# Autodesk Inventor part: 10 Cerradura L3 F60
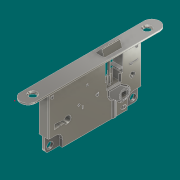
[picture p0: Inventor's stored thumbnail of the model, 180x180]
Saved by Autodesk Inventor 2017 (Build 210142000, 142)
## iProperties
Created: 2019-09
Part Number: 10 Cerradura L3 F60
Material: Acero inoxidable
Document SubType Name: Modeling
Designer: Alfredo Castillo
Density: 8 g/cm^3
Appearance: Semipulido
Mass: 1146.85 g
Surface Area: 306.712 cm^2
Volume: 143.356 cm^3
Author: Alfredo Castillo
Comments: Proveedor ITALINNEA Producto CERRADURA L3 F60 Y F30 CONTRAFUEGO Marca AGB (ITALIA) Modelo -Sin información- Material ACERO ZINCADO Terminación NIQUELADA Instalación Perforar madera por el canto de la 
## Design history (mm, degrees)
sketch "Boceto1"
  geometry: L1 (0, 0)-(0, 195); L2 (11, 11)-(11, 184); L3 (-11, 184)-(-11, 11); C1 r 4.5 at (0, 177.5); C2 r 4.5 at (0, 17.5); A1 r 11 centre (0, 11) between (-11, 11) and (11, 11); A2 r 11 centre (0, 184) between (11, 184) and (-11, 184); 1 further point
  constraints: 8 end point, 6 point on circle, 4 centre point, 4 point on line, 4 tangent, 1 midpoint, 1 parallel, 1 vertical
  dimensions: "d0" = 195 distance of L1.start L1.end; "d1" = 22 diameter of A2; "d2" = 9 diameter of C1; "d3" = 9 diameter of C2; "d4" = 160 distance of C2.centre C1.centre; "d5" = 17.5 distance of L1.end C1.centre (= -0.5 x d4 + 0.5 x d0)
extrude "Extrusión1" new body sketch "Boceto1" distance "d6" = 3; taper "d7" = 0 deg
chamfer "Chaflán1" distance "d8" = 1.5; stored, may be unused: second distance "d9" = 2, angle "d10" = 45 deg
fillet "Empalme1" dims "d11" = 1
sketch "Boceto2"
  geometry: L1 (-7, 162.5)-(7, 162.5); L2 (7, 162.5)-(7, 32.5); L3 (7, 32.5)-(-7, 32.5); L4 (-7, 32.5)-(-7, 162.5); L5 (11, 11)-(11, 184) reference; 1 further point
  constraints: 8 end point, 2 parallel, 1 horizontal, 1 perpendicular
  dimensions: "d12" = 130 distance of L1.end L2.end; "d13" = 32.5 distance from line of point (0, 0) L3; "d16" = 14 distance of L1.start L1.end; "d17" = 4 distance between parallel lines of L5 L2
extrude "Extrusión2" join sketch "Boceto2" distance "d14" = 76; taper "d15" = 0 deg
sketch "Boceto5"
  geometry: L1 (0, 130)-(76, 130) reference; L2 (76, 130)-(76, 0) reference; L3 (56, 130)-(76, 130); L4 (76, 130)-(76, 110); L5 (76, 20)-(76, 0); L6 (76, 0)-(56, 0); L7 (0, 0)-(76, 0) reference; A1 r 20 centre (76, 130) between (56, 130) and (76, 110); A2 r 20 centre (76, 0) between (76, 20) and (56, 0); 1 further point
  constraints: 8 end point, 4 point on circle, 3 collinear, 2 centre point, 2 point on line, 1 horizontal
  dimensions: "d21" = 20 radius of A1; "d22" = 20 radius of A2
sketch "Boceto3"
  geometry: L1 (0, 130)-(-76, 130) reference; L2 (-76, 0)-(-76, 130) reference; L3 (-76, 110)-(-76, 130); L4 (-76, 130)-(-56, 130); L5 (-76, 20)-(-76, 0); L6 (-76, 0)-(-56, 0); L7 (-56, 130)-(-56, 120); L8 (-76, 110)-(-66, 110); L9 (-76, 20)-(-66, 20); L10 (-56, 0)-(-56, 10); A1 r 10 centre (-66, 120) between (-66, 110) and (-56, 120); A2 r 10 centre (-66, 10) between (-56, 10) and (-66, 20); 1 further point
  constraints: 16 end point, 4 point on circle, 4 tangent, 2 centre point, 2 collinear, 2 horizontal, 2 perpendicular, 2 vertical, 1 point on line
  dimensions: "d233" = 10 distance of L4.end L7.end; "d234" = 10 distance of L3.start L8.end; "d235" = 10 distance of L5.start L9.end; "d236" = 10 distance of L6.end L10.end
extrude "Extrusión3" cut sketch "Boceto3" distance "d23" = 5; taper "d24" = 0 deg
fillet "Empalme2" dims "d27" = 5
hole "Agujero1" diameter "d31" = 9; stored, may be unused: countersink angle "d35" = 90 deg, drill point angle "d37" = 118 deg; dims "d29" = 7, "d30" = 7, "d32" = 6, "d33" = 4, "d34" = 2, "d36" = 8
hole "Agujero2" diameter "d40" = 9; stored, may be unused: countersink angle "d44" = 90 deg, drill point angle "d46" = 118 deg; dims "d38" = 7, "d39" = 7, "d41" = 6, "d42" = 4, "d43" = 2, "d45" = 8
fillet "Empalme4" dims "d47" = 1
fillet "Empalme5" dims "d48" = 1
fillet "Empalme7" dims "d50" = 1
sketch "Boceto6"
  geometry: L1 (-60.872, 105.498)-(-45.872, 105.498); L2 (-45.184, 109.399)-(-38, 99); L3 (0, 150.5)-(0, -22.5) reference; L4 (0, 129)-(-56, 129) reference; L5 (-61.027, 98.919)-(-51.427, 85.022); L6 (-45.668, 82)-(-38, 82); L7 (-38, 82)-(-38, 99); L8 (-57.646, 94.024)-(-76, 94.024); L9 (-76, 109)-(-76, 19) reference; L10 (-52.81, 87.024)-(-76, 87.024); L11 (-76, 94.024)-(-76, 87.024); A1 r 9.5 centre (-53, 104) between (-45.184, 109.399) and (-61.027, 98.919); A2 r 7 centre (-45.668, 89) between (-51.427, 85.022) and (-45.668, 82); 4 further points
  constraints: 16 end point, 4 point on circle, 3 horizontal, 3 point on line, 3 tangent, 2 centre point, 2 parallel, 1 collinear, 1 vertical
  dimensions: "d51" = 19 diameter of A1; "d54" = 53 distance from line of L3 A1.centre; "d55" = 25 distance from line of L4 A1.centre; "d59" = 7 radius of A2 (derived); "d60" = 7 distance between parallel lines of L8 L10; "d109" = 17 distance of L6.end L2.end; "d110" = 30 distance from line of L2.end L4; "d116" = 38 distance between parallel lines of L9 L7
extrude "Extrusión5" join sketch "Boceto6" distance "d61" = 1; taper "d62" = 0 deg
sketch "Boceto9"
  geometry: L1 (0, 7)-(1, 7) reference; L2 (0, 7)-(0, 0) reference; L3 (0, 0)-(1, 0) reference; L4 (1, 7)-(1, 0) reference; L5 (0, 7)-(1, 7) reference; 1 further point
extrude "Extrusión7" cut sketch "Boceto9" distance "d70" = 1; taper "d71" = 0 deg
fillet "Empalme13" dims "d72" = 3
fillet "Empalme14" dims "d73" = 1
sketch "Boceto10"
  geometry: L1 (-56.5, 107.5)-(-49.5, 107.5); L2 (-49.5, 107.5)-(-49.5, 100.5); L3 (-49.5, 100.5)-(-56.5, 100.5); L4 (-56.5, 100.5)-(-56.5, 107.5); L5 (-56.5, 107.5)-(-49.5, 100.5); L6 (-49.5, 107.5)-(-56.5, 100.5); 5 further points
  constraints: 12 end point, 2 midpoint, 2 parallel, 1 horizontal, 1 perpendicular, 1 other
  dimensions: "d74" = 7 distance of L2.end L3.end; "d75" = 7 distance of L1.end L2.end
extrude "Extrusión8" cut sketch "Boceto10" distance "d77" = 50; taper "d78" = 0 deg
sketch "Boceto11"
  geometry: C1 r 7 at (-53, 104); C2 r 6.75 at (-53, 104); 5 further points
  constraints: 2 centre point, 2 coincident, 1 other
  dimensions: "d79" = 14 diameter of C1; "d80" = 13.5 diameter of C2
extrude "Extrusión9" cut sketch "Boceto11" distance "d81" = 2; taper "d82" = 0 deg
fillet "Empalme15" dims "d83" = 1
sketch "Boceto12"
  geometry: L1 (-76, 4)-(-76, 124) reference; C1 r 3 at (-36, 116.356); 2 further points
  constraints: 1 centre point
  dimensions: "d84" = 6 diameter of C1; "d98" = 40 distance from line of L1 C1.centre
extrude "Extrusión10" join sketch "Boceto12" distance "d85" = 0.5; taper "d86" = 0 deg
fillet "Empalme16" dims "d87" = 1
sketch "Boceto13"
  geometry: C1 r 3 at (-36, 116.356) reference; C2 r 3.125 at (-36, 116.356); 1 further point
  constraints: 1 centre point, 1 coincident
  dimensions: "d88" = 6.25 diameter of C2
extrude "Extrusión11" cut sketch "Boceto13" distance "d89" = 2; taper "d90" = 0 deg
sketch "Boceto14"
  geometry: L1 (-48.58, 7.516)-(-41.58, 7.516); L2 (-48.58, 7.516)-(-34.961, 7.516); L3 (-41.58, 7.516)-(-42.818, 21.056); L4 (-47.814, 16.265)-(-46.64, 16.265); L5 (-46.64, 16.265)-(-46.64, 13.958); L6 (-46.64, 13.958)-(-48.006, 14.078); L7 (-48.58, 7.516)-(-48.006, 14.078); L8 (-47.814, 16.265)-(-47.393, 21.083); A1 r 5 centre (-45.08, 25.516) between (-42.818, 21.056) and (-47.393, 21.083); 1 further point
  constraints: 16 end point, 3 horizontal, 3 perpendicular, 2 point on circle, 1 centre point
  dimensions: "d91" = 10 diameter of A1; "d92" = 7 distance of L1.start L1.end; "d93" = 3.5 horizontal distance of L1.start A1.centre; "d95" = 18 distance from line of L1 A1.centre
extrude "Extrusión12" cut sketch "Boceto14" distance "d96" = 50; taper "d97" = 0 deg
sketch "Boceto15"
  geometry: L1 (-21.5, 124)-(-20, 124); L2 (-20, 124)-(-20, 112); L3 (-20, 112)-(-21.5, 112); L4 (-21.5, 112)-(-21.5, 124); L5 (0, 150.5)-(0, -22.5) reference; L6 (0, 129)-(-56, 129) reference; 2 further points
  constraints: 8 end point, 2 parallel, 1 horizontal, 1 perpendicular
  dimensions: "d99" = 1.5 distance of L2.end L3.end; "d100" = 12 distance of L1.end L2.end; "d101" = 20 distance between parallel lines of L5 L2; "d104" = 5 distance between parallel lines of L6 L1
extrude "Extrusión13" cut sketch "Boceto15" distance "d102" = 4; taper "d103" = 0 deg
sketch "Boceto16"
  geometry: L1 (-20, 112)-(-21.5, 112) reference; L2 (-20, 112)-(-21.5, 112); L3 (-21.5, 112)-(-21.5, 115); L4 (-21.5, 115)-(-20, 115); L5 (-20, 115)-(-20, 112); 1 further point
  constraints: 8 end point, 2 parallel, 1 horizontal, 1 perpendicular
  dimensions: "d105" = 3 distance of L2.end L3.end
extrude "Extrusión14" join sketch "Boceto16" distance "d106" = 6; taper "d107" = 0 deg
sketch "Boceto17"
  geometry: 1 further point
sketch "Boceto18"
  geometry: L1 (-6, 136.5)-(6, 136.5); L2 (6, 136.5)-(6, 111.5); L3 (6, 111.5)-(-6, 111.5); L4 (-6, 136.5)-(6, 111.5); L5 (6, 136.5)-(-6, 111.5); L6 (-6, 142.5)-(-6, 52.5) reference; L7 (-6, 111.5)-(-6, 121); L8 (-6, 127)-(-6, 136.5); A1 r 3.5 centre (-7.803, 124) between (-6, 121) and (-6, 127); 5 further points
  constraints: 14 end point, 3 parallel, 2 midpoint, 2 point on circle, 2 point on line, 1 centre point, 1 horizontal, 1 perpendicular
  dimensions: "d111" = 12 distance of L2.end L3.end; "d112" = 25 distance of L1.end L2.end; "d113" = 38.5 vertical distance of point (-6, 162.5) point (0, 124); "d117" = 6 distance of L8.start L7.end; "d118" = 3.5 radius of A1
extrude "Extrusión15" cut sketch "Boceto18" distance "d114" = 30; taper "d115" = 0 deg
sketch "Boceto19"
  geometry: L1 (-27, 103)-(-27, 78) reference; L2 (3, 78)-(-27, 78) reference; L3 (-27, 103)-(-3, 103); L4 (-3, 103)-(-3, 78); L5 (-3, 78)-(-27, 78); L6 (-27, 78)-(-27, 103); 1 further point
  constraints: 8 end point, 2 parallel, 1 horizontal, 1 perpendicular, 1 point on line
  dimensions: "d119" = 24 distance of L4.end L5.end
extrude "Extrusión16" cut sketch "Boceto19" distance "d120" = 10; taper "d121" = 0 deg
sketch "Boceto20"
  geometry: L1 (-1, 121.709)-(-1, 119.5); L2 (-1, 119.5)-(-7, 113.5); L3 (-1, 119.5)-(6.071, 119.5); L4 (-1, 126.291)-(-1, 128.291); L5 (-1, 128.291)-(-7, 134.291); L6 (-7, 111.5)-(-7, 136.5) reference; L7 (-7, 134.291)-(-7, 113.5); A1 r 2.5 centre (0, 124) between (-1, 121.709) and (-1, 126.291); 2 further points
  constraints: 12 end point, 2 point on circle, 2 point on line, 2 vertical, 1 centre point, 1 horizontal
  dimensions: "d122" = 5 diameter of A1; "d125" = 135 deg angle of L2 L3; "d126" = 2 distance of L4.start L4.end; "d127" = 135 deg angle of L5 L4
extrude "Extrusión17" cut sketch "Boceto20" distance "d128" = 10; taper "d129" = 0 deg
sketch "Boceto21"
  geometry: C1 r 1.75 at (0, 124); A1 r 2.5 centre (0, 124) between (-1, 126.291) and (-1, 121.709) reference; 1 further point
  constraints: 1 centre point, 1 coincident
  dimensions: "d130" = 3.5 diameter of C1
extrude "Extrusión18" join sketch "Boceto21" distance "d131" = 30; taper "d132" = 0 deg
sketch "Boceto22"
  geometry: C1 r 1.75 at (0, 124) reference; C2 r 2 at (0, 124); 1 further point
  constraints: 1 centre point, 1 coincident
  dimensions: "d133" = 4 diameter of C2
extrude "Extrusión19" cut sketch "Boceto22" distance "d134" = 20; taper "d135" = 0 deg
sketch "Boceto24"
  geometry: L1 (-6, 136.5)-(6, 136.5) reference; L2 (6, 111.5)-(-6, 111.5) reference; L3 (6, 136.5)-(6, 111.5) reference; L4 (-6, 111.5)-(-6, 121) reference; L5 (-6, 127)-(-6, 136.5) reference; A1 r 3.5 centre (-7.803, 124) between (-6, 121) and (-6, 127) reference; 1 further point
extrude "Extrusión20" join sketch "Boceto24" distance "d136" = 10; taper "d137" = 0 deg
sketch "Boceto25"
  geometry: L1 (12, 0)-(0, 0) reference; L2 (0, 0)-(13.054, 0); L3 (8.391, -10)-(12, 0); L4 (12, 0)-(12, -10); L5 (8.391, -10)-(12, -10); 2 further points
  constraints: 8 end point, 2 horizontal
extrude "Extrusión21" cut sketch "Boceto25" distance "d139" = 25; taper "d140" = 0 deg
sketch "Boceto27"
  geometry: L1 (8.391, 0)-(0, 0) reference; L2 (8.391, 0)-(0, 10); L3 (0, 10)-(0, 0) reference; L4 (0, 10)-(0, 0); L5 (0, 0)-(8.391, 0); 1 further point
  constraints: 6 end point, 1 collinear, 1 perpendicular
extrude "Extrusión22" cut sketch "Boceto27" distance "d141" = 25; taper "d142" = 0 deg
fillet "Empalme17" dims "d143" = 1
sketch "Boceto29"
  geometry: L1 (-7, 136.5)-(6, 136.5) reference; L2 (6, 136.5)-(6, 111.5) reference; L3 (-7, 111.5)-(6, 111.5) reference; L4 (-7, 111.5)-(-7, 113.5) reference; L5 (-1, 119.5)-(-7, 113.5) reference; L6 (-1, 121.709)-(-1, 119.5) reference; L7 (-7, 134.291)-(-7, 136.5) reference; L8 (-7, 134.291)-(-1, 128.291) reference; L9 (-1, 128.291)-(-1, 126.291) reference; L10 (0, 128.706)-(-6, 134.706); L11 (-6, 134.706)-(-6, 135.5); L12 (-6, 135.5)-(5, 135.5); L13 (5, 135.5)-(5, 112.5); L14 (5, 112.5)-(-6, 112.5); L15 (-6, 112.5)-(-6, 113.086); L16 (-6, 113.086)-(0, 119.086); L17 (0, 119.086)-(0, 122.5); L18 (0, 125.5)-(0, 128.706); A1 r 2.5 centre (0, 124) between (-1, 126.291) and (-1, 121.709) reference; A2 r 2.5 centre (0, 124) between (-1, 121.709) and (-1, 126.291); A3 r 1.5 centre (0, 124) between (0, 125.5) and (0, 122.5); 1 further point
  constraints: 20 end point, 4 point on circle, 2 centre point, 1 coincident, 9 other
  dimensions: "d147" = 1 distance between parallel lines of L8 L10
extrude "Extrusión24" cut sketch "Boceto29" distance "d148" = 11; taper "d149" = 0 deg
sketch "Boceto30"
  geometry: L1 (-1, 128.291)-(-1, 126.291) reference; L2 (-7, 134.291)-(-1, 128.291) reference; L3 (-7, 113.5)-(-7, 134.291) reference; L4 (-1, 119.5)-(-7, 113.5) reference; L5 (-1, 121.709)-(-1, 119.5) reference; A1 r 2.5 centre (0, 124) between (-1, 126.291) and (-1, 121.709) reference; 1 further point
extrude "Extrusión25" cut sketch "Boceto30" distance "d150" = 1; taper "d151" = 0 deg
sketch "Boceto31"
  geometry: L1 (1, 16.555)-(7, 10.555) reference; L2 (2.731, 15.06)-(4.731, 15.06); L3 (7, 1.764)-(1, -4.236) reference; L4 (1, 14.764)-(1, 16.555) reference; L5 (7, 10.555)-(7, 8.555) reference; L6 (6.069, 4.676)-(6.069, 0.833); L7 (6, 7.764)-(6.661, 10.894); L8 (4.551, 13.004)-(3.612, 8.555); L9 (3.569, 8.142)-(3.569, -1.667); L10 (4.551, 13.004)-(6.661, 10.894); L11 (3.569, -1.667)-(6.069, 0.833); A1 r 2.5 centre (8, 6.264) between (7, 8.555) and (7, 3.973) reference; A2 r 2.5 centre (8, 6.264) between (6, 7.764) and (6.069, 4.676); A3 r 2 centre (5.569, 8.142) between (3.612, 8.555) and (3.569, 8.142); 2 further points
  constraints: 15 end point, 6 point on circle, 6 point on line, 2 centre point, 2 tangent, 1 coincident, 1 concentric, 1 horizontal, 1 vertical
  dimensions: "d163" = 2.5 distance between parallel lines of L7 L8; "d166" = 2 radius of A3
extrude "Extrusión26" join sketch "Boceto31" distance "d164" = 5; taper "d165" = 0 deg
sketch "Boceto32"
  geometry: L1 (-27, 103)-(-27, 78) reference; L2 (-38, 99)-(-38, 95.066) reference; L3 (-27, 103)-(-38, 103); L4 (-38, 103)-(-38, 95.066); L5 (-38, 95.066)-(-27, 95.066); L6 (-27, 95.066)-(-27, 103); 1 further point
  constraints: 8 end point, 2 parallel, 1 horizontal, 1 perpendicular
extrude "Extrusión27" join sketch "Boceto32" distance "d167" = 1; taper "d168" = 0 deg
sketch "Boceto33"
  geometry: L1 (-42.818, 21.056)-(-41.58, 7.516) reference; L2 (-47.814, 16.265)-(-47.393, 21.083) reference; A1 r 5 centre (-45.08, 25.516) between (-42.818, 21.056) and (-47.393, 21.083) reference; A2 r 5.5 centre (-45.08, 25.516) between (-42.769, 20.524) and (-47.44, 20.548); 1 further point
  constraints: 2 point on circle, 2 point on line, 1 centre point, 1 coincident
  dimensions: "d169" = 11 diameter of A2
extrude "Extrusión28" join sketch "Boceto33" distance "d170" = 1.5; taper "d171" = 0 deg
fillet "Empalme18" dims "d172" = 1
sketch "Boceto37"
  geometry: L1 (-16.692, 7.516)-(-6.692, 7.516); L2 (-6.692, 7.516)-(-6.692, 17.516); L3 (-6.692, 17.516)-(-9.192, 17.516); L4 (-9.192, 17.516)-(-9.192, 20.016); L5 (-14.192, 20.016)-(-14.192, 17.516); L6 (-14.192, 17.516)-(-16.692, 17.516); L7 (-16.692, 17.516)-(-16.692, 7.516); L8 (-54.907, 79.819)-(-49.907, 79.819); L9 (-49.907, 79.819)-(-49.907, 72.319); L10 (-49.907, 72.319)-(-54.907, 72.319); L11 (-54.907, 72.319)-(-54.907, 79.819); L12 (-41.58, 7.516)-(-48.58, 7.516) reference; L13 (-30.41, 60)-(-30.41, 62.5); L14 (-30.41, 62.5)-(-27.91, 62.5); L15 (-35.41, 62.5)-(-35.41, 60); L16 (-37.91, 62.5)-(-35.41, 62.5); L17 (-27.91, 62.5)-(-27.91, 72.5); L18 (-27.91, 72.5)-(-37.91, 72.5); L19 (-37.91, 72.5)-(-37.91, 62.5); L20 (-46.58, 40.926)-(-41.58, 40.926); L21 (-41.58, 40.926)-(-41.58, 33.426); L22 (-41.58, 33.426)-(-46.58, 33.426); L23 (-46.58, 33.426)-(-46.58, 40.926); L24 (-46.58, 53.235)-(-41.58, 53.235); L25 (-41.58, 53.235)-(-41.58, 45.735); L26 (-41.58, 45.735)-(-46.58, 45.735); L27 (-46.58, 45.735)-(-46.58, 53.235); L28 (-15.016, 120.842)-(-11.016, 120.842); L29 (-11.016, 120.842)-(-11.016, 113.342); L30 (-15.016, 115.842)-(-15.016, 120.842); L31 (-15.016, 115.842)-(-14.016, 115.842); L32 (-14.016, 115.842)-(-14.016, 113.342); L33 (-76, 109)-(-76, 19) reference; L34 (-69.311, 107.84)-(-69.311, 100.34); L35 (-66.811, 105.34)-(-66.811, 102.84); L36 (-71.811, 102.84)-(-71.811, 105.34); C1 r 2.5 at (-70.382, 67.5); C2 r 1.75 at (-59, 66.518); C3 r 1.75 at (-41.58, 60); C4 r 1.75 at (-59, 40.842); A1 r 2.5 centre (-11.692, 20.016) between (-9.192, 20.016) and (-14.192, 20.016); A2 r 2.5 centre (-32.91, 60) between (-35.41, 60) and (-30.41, 60); A3 r 1.5 centre (-12.516, 113.342) between (-14.016, 113.342) and (-11.016, 113.342); A4 r 2.5 centre (-69.311, 105.34) between (-66.811, 105.34) and (-71.811, 105.34); A5 r 2.5 centre (-69.311, 102.84) between (-71.811, 102.84) and (-66.811, 102.84); 4 further points
  constraints: 70 end point, 13 perpendicular, 12 point on circle, 10 parallel, 9 centre point, 9 tangent, 7 point on line, 6 horizontal, 1 midpoint, 1 vertical
  dimensions: "d187" = 10 distance of L1.start L1.end; "d188" = 10 distance of L6.end L1.start; "d189" = 2.5 distance of L5.end L6.end; "d190" = 2.5 distance of L2.end L3.end; "d191" = 2.5 distance from line of L3 A1.centre; "d192" = 0 distance between parallel lines of L12 L1; "d193" = 10 distance of L17.end L18.end; "d194" = 10 distance of L14.end L17.end; "d195" = 2.5 distance of L13.end L14.end; "d196" = 2.5 distance of L16.start L15.start; "d197" = 2.5 distance from line of L16 A2.centre; "d198" = 5 distance of L8.start L8.end; "d199" = 7.5 distance of L10.end L8.start; "d200" = 5 diameter of C1; "d201" = 3.5 diameter of C2; "d202" = 3.5 diameter of C3; "d203" = 3.5 diameter of C4; "d204" = 7.5 distance of L20.end L21.end; "d205" = 5 distance of L21.end L22.end; "d206" = 7.5 distance of L24.end L25.end; "d207" = 5 distance of L25.end L26.end; "d208" = 4 distance of L28.start L28.end; "d209" = 5 distance of L30.start L28.start; "d210" = 7.5 distance of L28.end L29.end; "d212" = 1.5 radius of A3; "d213" = 17 distance from line of L33 C2.centre; "d214" = 17 distance from line of L33 C4.centre; "d215" = 7.5 distance of L34.start L34.end; "d216" = 2.5 radius of A5
extrude "Extrusión32" cut sketch "Boceto37" distance "d217" = 5; taper "d218" = 0 deg
sketch "Boceto38"
  geometry: C1 r 1.75 at (0, 0) reference; C2 r 1.75 at (17.42, -6.517) reference; C3 r 1.75 at (0, -25.676) reference; 1 further point
extrude "Extrusión33" join sketch "Boceto38" distance "d219" = 4; taper "d220" = 0 deg
fillet "Empalme22" dims "d221" = 1
sketch "Boceto40"
  geometry: C1 r 3.125 at (0, 0) reference; 1 further point
extrude "Extrusión34" cut sketch "Boceto40" distance "d222" = 20; taper "d223" = 0 deg
fillet "Empalme23" dims "d224" = 0.75
sketch "Boceto41"
  geometry: C1 r 2.25 at (-69.311, 105.34); A1 r 2.5 centre (-69.311, 105.34) between (-66.811, 105.34) and (-71.811, 105.34) reference; 1 further point
  constraints: 1 centre point, 1 coincident, 1 horizontal alignment, 2 other
  dimensions: "d225" = 0.25 dimension on C1
extrude "Extrusión35" join sketch "Boceto41" distance "d226" = 5; taper "d227" = 0 deg
fillet "Empalme24" dims "d228" = 0.25
sketch "Boceto42"
  geometry: C1 r 2 at (-17.064, 53.27); 1 further point
  constraints: 1 centre point
  dimensions: "d229" = 4 diameter of C1
extrude "Extrusión36" join sketch "Boceto42" distance "d230" = 1; taper "d231" = 0 deg
fillet "Empalme25" dims "d232" = 1
node "Plano de trabajo4"
mirror "Simetría2"
mirror "Simetría3"
sketch "Boceto43"
  geometry: C1 r 1.75 at (0, 0); A1 r 1.75 centre (0, 0) between (0, 1.75) and (0, -1.75) reference; 3 further points
  constraints: 2 coincident, 1 centre point, 1 concentric, 1 vertical alignment, 2 other
extrude "Extrusión37" join sketch "Boceto43" stored distance "d237" = 1; taper "d238" = 0 deg
sketch "Boceto45"
  geometry: L1 (0, 27)-(0, -29) reference; L2 (14, -29)-(14, 27) reference; L3 (0, 5.558)-(14, 5.558); L4 (14, 5.558)-(14, 7.058); L5 (14, 7.058)-(0, 7.058); L6 (0, 7.058)-(0, 5.558); L7 (13.9, 5.658)-(0.1, 5.658); L8 (0.1, 5.658)-(0.1, 6.958); L9 (0.1, 6.958)-(13.9, 6.958); L10 (13.9, 6.958)-(13.9, 5.658); 1 further point
  constraints: 16 end point, 4 parallel, 2 perpendicular, 2 point on line, 1 horizontal, 3 other
  dimensions: "d243" = 1.5 distance of L4.end L3.end; "d244" = 0.1 distance between parallel lines of L3 L7
extrude "Extrusión39" join sketch "Boceto45" distance "d245" = 5; taper "d246" = 0 deg
fillet "Empalme27" dims "d247" = 1
sketch "Boceto46"
  geometry: L1 (18.5, 18.5)-(11.5, 18.5) reference; L2 (18.5, 25.5)-(18.5, 18.5) reference; L3 (11.5, 25.5)-(18.5, 25.5) reference; L4 (11.5, 18.5)-(11.5, 25.5) reference; 1 further point
extrude "Extrusión40" cut sketch "Boceto46" distance "d248" = 20; taper "d249" = 0 deg
mirror "Simetría4"
fillet "Empalme28" dims "d250" = 1
fillet "Empalme29" dims "d251" = 4
fillet "Empalme30" dims "d252" = 2
mirror "Simetría5"
mirror "Simetría6"
sketch "Boceto47"
  geometry: L1 (66.811, 105.34)-(66.811, 102.84) reference; L2 (71.811, 102.84)-(71.811, 105.34) reference; A1 r 2.5 centre (69.311, 102.84) between (66.811, 102.84) and (71.811, 102.84) reference; A2 r 2.5 centre (69.311, 105.34) between (71.811, 105.34) and (66.811, 105.34) reference; 1 further point
extrude "Extrusión41" cut sketch "Boceto47" distance "d253" = 5; taper "d254" = 0 deg
mirror "Simetría7"
sketch "Boceto48"
  geometry: L1 (2.054, 124.448)-(6.054, 124.448); L2 (6.054, 124.448)-(6.054, 122.948); L3 (6.054, 122.948)-(2.054, 122.948); L4 (2.054, 122.948)-(2.054, 124.448); L5 (5.332, 6.158)-(9.332, 6.158); L6 (9.332, 6.158)-(9.332, 4.658); L7 (9.332, 4.658)-(5.332, 4.658); L8 (5.332, 4.658)-(5.332, 6.158); L9 (33.506, 69.486)-(37.506, 69.486); L10 (37.506, 69.486)-(37.506, 67.986); L11 (37.506, 67.986)-(33.506, 67.986); L12 (33.506, 67.986)-(33.506, 69.486); L13 (46.58, 45.735)-(46.58, 53.235) reference; L14 (38.55, 47.356)-(42.55, 47.356); L15 (42.55, 47.356)-(42.55, 45.856); L16 (42.55, 45.856)-(38.55, 45.856); L17 (38.55, 45.856)-(38.55, 47.356); C1 r 1.5 at (35.557, 41.585); C2 r 1.5 at (20.31, 50.692); 1 further point
  constraints: 32 end point, 8 parallel, 4 horizontal, 4 perpendicular, 2 centre point
  dimensions: "d255" = 4 distance of L2.end L3.end; "d256" = 1.5 distance of L1.end L2.end; "d257" = 4 distance of L6.end L7.end; "d258" = 1.5 distance of L5.end L6.end; "d259" = 4 distance of L10.end L11.end; "d260" = 1.5 distance of L9.end L10.end; "d261" = 4 distance of L15.end L16.end; "d262" = 1.5 distance of L14.end L15.end; "d263" = 3 diameter of C1; "d264" = 3 diameter of C2
extrude "Extrusión42" cut sketch "Boceto48" distance "d265" = 1; taper "d266" = 0 deg
fillet "Empalme31" dims "d267" = 1
fillet "Empalme32" dims "d268" = 1
sketch "Boceto49"
  geometry: C1 r 1 at (17.064, 53.27) reference; C2 r 1.5 at (17.064, 53.27); 1 further point
  constraints: 1 centre point, 1 coincident
  dimensions: "d269" = 3 diameter of C2
extrude "Extrusión43" join sketch "Boceto49" distance "d270" = 1; taper "d271" = 0 deg
fillet "Empalme33" dims "d272" = 1
sketch "Boceto50"
  geometry: L1 (2.554, 123.698)-(5.554, 123.698); L2 (5.554, 123.698)-(5.554, 121.448); L3 (2.554, 121.448)-(2.554, 123.698); L4 (6.054, 124.448)-(6.054, 122.948) reference; L5 (6.054, 122.948)-(2.054, 122.948) reference; L6 (5.832, 5.408)-(8.832, 5.408); L7 (8.832, 5.408)-(8.832, 3.158); L8 (5.832, 3.158)-(5.832, 5.408); L9 (9.332, 6.158)-(9.332, 4.658) reference; L10 (9.332, 4.658)-(5.332, 4.658) reference; L11 (33.944, 68.79)-(36.944, 68.79); L12 (33.944, 66.54)-(33.944, 68.79); L13 (36.944, 68.79)-(36.944, 66.54); A1 r 1.5 centre (4.054, 121.448) between (2.554, 121.448) and (5.554, 121.448); A2 r 1.5 centre (7.332, 3.158) between (5.832, 3.158) and (8.832, 3.158); A3 r 1.5 centre (35.444, 66.54) between (33.944, 66.54) and (36.944, 66.54); 1 further point
  constraints: 18 end point, 6 point on circle, 6 tangent, 3 centre point, 3 horizontal, 3 parallel, 3 perpendicular
  dimensions: "d273" = 3 distance of L1.start L1.end; "d274" = 0.5 distance between parallel lines of L4 L2; "d275" = 1.5 distance from line of L5 A1.centre; "d276" = 3 distance of L6.start L6.end; "d277" = 0.5 distance between parallel lines of L9 L7; "d278" = 1.5 distance from line of L10 A2.centre; "d279" = 0.75 distance between parallel lines of L10 L6; "d280" = 0.75 distance between parallel lines of L1 L5; "d285" = 3 distance of L11.start L11.end
extrude "Extrusión44" join sketch "Boceto50" distance "d281" = 1; taper "d282" = 0 deg
fillet "Empalme34" dims "d283" = 0.5
fillet "Empalme35" dims "d284" = 0.5
fillet "Empalme36" dims "d286" = 0.5
node "Sólido1"
node "Contorno proyectado1"
node "Contorno proyectado3"
node "Contorno proyectado4"
node "Contorno proyectado5"
node "Contorno proyectado6"
other parameters: "d94" = 85 deg
